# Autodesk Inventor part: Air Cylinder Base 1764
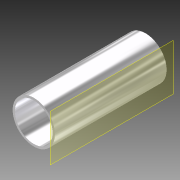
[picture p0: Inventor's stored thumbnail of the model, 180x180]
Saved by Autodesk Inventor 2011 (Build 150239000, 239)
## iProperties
Created: 2010-01
Part Number: Air Cylinder Base 1764
Document SubType Name: Modeling
Designer: cmcfadden
Density: 1 g/cm^3
Author: cmcfadden
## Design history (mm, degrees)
sketch "Sketch1"
  geometry: C1 r 26.416 at (10.426, -13.014); 1 further point
  constraints: 1 centre point
  dimensions: "d0" = 52.832 diameter of C1
extrude "Extrusion1" new body sketch "Sketch1" distance "d1" = 139.7508; taper "d2" = 0 deg
workplane "Work Plane1"
sketch "Sketch2"
  geometry: 1 further point
sketch "Sketch3"
  geometry: C1 r 26.416 at (0, 0) reference; C2 r 23.647 at (0, 0); 1 further point
  constraints: 1 centre point, 1 coincident
  dimensions: "d14" = 47.2948 diameter of C2
extrude "Extrusion2" cut sketch "Sketch3" stored distance "d15" = 25.4; taper "d16" = 0 deg
body "Solid1"
other parameters: "d3" = 38.1
